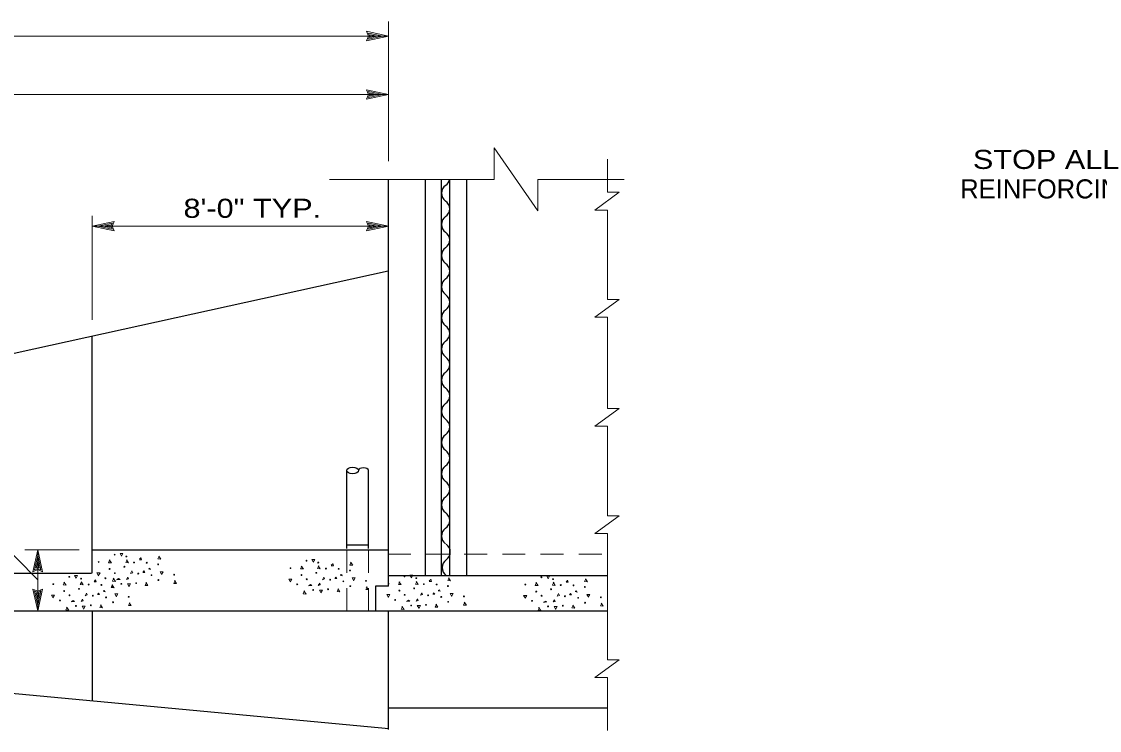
# Model space of a CAD drawing. Extents: x -22.3 to 19.7, y -11.8 to 18.2.
# Drawn here: x 5.45 to 12.51, y 1.6 to 6.24 of the extents above; entities that cross this region are included whole.
import ezdxf
from ezdxf.enums import TextEntityAlignment as Align

# ---------------------------------------------------------------- set-up
doc = ezdxf.new("R2010")
doc.units = 0
doc.header["$LTSCALE"] = 0.05
doc.linetypes.add('MEDIUM_DASHED', pattern=[4.5, 3, -1.5])
doc.layers.add('1', color=7, linetype='Continuous', lineweight=13)
doc.layers.add('2', color=7, linetype='Continuous', lineweight=13)

msp = doc.modelspace()

# ---------------------------------------------------------------- linework, layer by layer
at = {"layer": '1'}
for p, q in [((7.85258, 5.32831), (7.85258, 6.24331)), ((5.11858, 6.14831), (7.85258, 6.14831)), ((7.85258, 6.14831), (7.70858, 6.17931)), ((7.85258, 6.14831), (7.70858, 6.11731)), ((7.81558, 6.14831), (7.72158, 6.16831)), ((7.73058, 6.14831), (7.72158, 6.16831)), ((7.81558, 6.14831), (7.72158, 6.12831)), ((7.72158, 6.12831), (7.73058, 6.14831)), ((7.77958, 6.14831), (7.73458, 6.15731)), ((7.73858, 6.14831), (7.73458, 6.15731)), ((7.77958, 6.14831), (7.73458, 6.13831)), ((7.73458, 6.13831), (7.73858, 6.14831)), ((7.85258, 5.76631), (7.70858, 5.79731)), ((7.81558, 5.76631), (7.72158, 5.78631)), ((7.73058, 5.76631), (7.72158, 5.78631)), ((5.09858, 5.76631), (7.85258, 5.76631)), ((7.85258, 5.76631), (7.70858, 5.73531)), ((7.81558, 5.76631), (7.72158, 5.74631)), ((7.72158, 5.74631), (7.73058, 5.76631)), ((7.77958, 5.76631), (7.73458, 5.77531)), ((7.73858, 5.76631), (7.73458, 5.77531)), ((7.77958, 5.76631), (7.73458, 5.75631)), ((7.73458, 5.75631), (7.73858, 5.76631)), ((8.54558, 5.21031), (8.54558, 5.41631)), ((8.83058, 5.00331), (8.54558, 5.41631)), ((9.28658, 5.12531), (9.28658, 5.34231)), ((7.46758, 5.21031), (8.54558, 5.21031)), ((8.83058, 5.00331), (8.83058, 5.21031)), ((8.83058, 5.21031), (9.39658, 5.21031)), ((9.20458, 5.00931), (9.36258, 5.12531)), ((9.28658, 5.12531), (9.36258, 5.12531)), ((5.91358, 4.29031), (5.91358, 4.97031)), ((9.20458, 5.00931), (9.28658, 5.00931)), ((9.28658, 4.42331), (9.28658, 5.00931)), ((5.91358, 4.90331), (6.05758, 4.93431)), ((5.91358, 4.90331), (7.85258, 4.90331)), ((5.91358, 4.90331), (6.05758, 4.87231)), ((5.95058, 4.90331), (6.04458, 4.92331)), ((5.95058, 4.90331), (6.04458, 4.88331)), ((5.98658, 4.90331), (6.03158, 4.91331)), ((5.98658, 4.90331), (6.03158, 4.89431)), ((6.03158, 4.91331), (6.02758, 4.90331)), ((6.02758, 4.90331), (6.03158, 4.89431)), ((6.04458, 4.92331), (6.03558, 4.90331)), ((6.03558, 4.90331), (6.04458, 4.88331)), ((7.85258, 4.90331), (7.70858, 4.93431)), ((7.85258, 4.90331), (7.70858, 4.87231)), ((7.81558, 4.90331), (7.72158, 4.92331)), ((7.73058, 4.90331), (7.72158, 4.92331)), ((7.81558, 4.90331), (7.72158, 4.88331)), ((7.72158, 4.88331), (7.73058, 4.90331)), ((7.77958, 4.90331), (7.73458, 4.91231)), ((7.73858, 4.90331), (7.73458, 4.91231)), ((7.77958, 4.90331), (7.73458, 4.89331)), ((7.73458, 4.89331), (7.73858, 4.90331)), ((9.20458, 4.30731), (9.36258, 4.42331)), ((9.28658, 4.42331), (9.36258, 4.42331)), ((9.20458, 4.30731), (9.28658, 4.30731)), ((9.28658, 3.71031), (9.28658, 4.30731)), ((9.20458, 3.59431), (9.36258, 3.71031)), ((9.28658, 3.71031), (9.36258, 3.71031)), ((9.20458, 3.59431), (9.28658, 3.59431)), ((9.28658, 3.00831), (9.28658, 3.59431)), ((9.20458, 2.89231), (9.36258, 3.00831)), ((9.28658, 3.00831), (9.36258, 3.00831)), ((9.20458, 2.89231), (9.28658, 2.89231)), ((9.28658, 2.06531), (9.28658, 2.89231)), ((5.82758, 2.78531), (5.47258, 2.78531)), ((5.55658, 2.78531), (5.52558, 2.64131)), ((5.55658, 2.38431), (5.55658, 2.78531)), ((5.55658, 2.78531), (5.58758, 2.64131)), ((5.55658, 2.74831), (5.53658, 2.65431)), ((5.55658, 2.71231), (5.54758, 2.66731)), ((5.55658, 2.74831), (5.57658, 2.65431)), ((5.55658, 2.71231), (5.56658, 2.66731)), ((5.55658, 2.66331), (5.53658, 2.65431)), ((5.55658, 2.67131), (5.54758, 2.66731)), ((5.56658, 2.66731), (5.55658, 2.67131)), ((5.57658, 2.65431), (5.55658, 2.66331)), ((5.55658, 2.38431), (5.52558, 2.52831)), ((5.55658, 2.42131), (5.53658, 2.51531)), ((5.53658, 2.51531), (5.55658, 2.50631)), ((5.55658, 2.45731), (5.54658, 2.50231)), ((5.54658, 2.50231), (5.55658, 2.49831)), ((5.55658, 2.38431), (5.58758, 2.52831)), ((5.55658, 2.42131), (5.57658, 2.51531)), ((5.55658, 2.50631), (5.57658, 2.51531)), ((5.55658, 2.45731), (5.56558, 2.50231)), ((5.55658, 2.49831), (5.56558, 2.50231)), ((9.20458, 1.94931), (9.36258, 2.06531)), ((9.28658, 2.06531), (9.36258, 2.06531)), ((9.20458, 1.94931), (9.28658, 1.94931)), ((9.28658, 1.60231), (9.28658, 1.94931))]:
    msp.add_line(p, q, dxfattribs=at)
at = {"layer": '1', "lineweight": 25}
for p, q in [((7.85258, 2.54631), (7.85258, 5.21031)), ((8.09558, 2.61731), (8.09558, 5.21031)), ((8.19958, 2.61731), (8.19958, 5.21031)), ((8.25358, 2.61731), (8.25358, 5.21031)), ((8.36558, 2.61731), (8.36558, 5.21031)), ((5.16258, 4.01931), (7.85058, 4.61031)), ((5.91358, 2.63231), (5.91358, 4.18131)), ((7.57958, 2.79431), (7.57958, 3.30431)), ((7.72158, 2.79431), (7.72158, 3.30431)), ((5.91358, 2.78531), (7.84858, 2.78531)), ((7.57958, 2.81831), (7.72158, 2.81831)), ((5.16558, 2.63231), (5.90958, 2.63231)), ((7.85258, 2.61731), (9.28658, 2.61731)), ((5.16558, 2.38431), (9.28558, 2.38431)), ((5.91358, 2.38431), (5.91358, 1.79631)), ((7.85258, 1.60831), (7.85258, 2.38431)), ((5.16458, 1.86731), (7.85458, 1.61431)), ((7.85258, 1.75131), (9.28558, 1.75131))]:
    msp.add_line(p, q, dxfattribs=at)
at = {"layer": '1', "linetype": 'MEDIUM_DASHED'}
for p, q in [((7.57958, 2.38431), (7.57958, 2.79431)), ((7.72158, 2.38431), (7.72158, 2.79431)), ((7.84858, 2.75631), (9.28658, 2.75631))]:
    msp.add_line(p, q, dxfattribs=at)
at = {"layer": '1'}
for points in [[(7.70858, 6.11731), (7.72258, 6.14831), (7.70858, 6.17931)], [(7.70858, 5.73531), (7.72258, 5.76631), (7.70858, 5.79731)], [(6.05758, 4.93431), (6.04358, 4.90331), (6.05758, 4.87231)], [(7.70858, 4.87231), (7.72258, 4.90331), (7.70858, 4.93431)], [(5.55658, 2.58831), (4.71458, 3.44231), (4.71458, 3.65231)], [(5.58758, 2.64131), (5.55658, 2.65531), (5.52558, 2.64131)], [(5.52558, 2.52831), (5.55658, 2.51431), (5.58758, 2.52831)]]:
    msp.add_lwpolyline(points, dxfattribs=at)
at = {"layer": '1', "lineweight": 25}
msp.add_lwpolyline([(7.85258, 2.54631), (7.76758, 2.54631), (7.76758, 2.38331)], dxfattribs=at)
for centre, start, end in [((8.26108, 5.11931), 124.0772, 235.92281), ((8.19208, 5.22131), 304.0772, 349.69515), ((8.19208, 5.01731), 304.0772, 55.92281), ((8.26108, 4.91531), 124.0772, 235.92281), ((8.19208, 4.81331), 304.0772, 55.92281), ((8.26108, 4.71131), 124.0772, 235.92281), ((8.19208, 4.60931), 304.0772, 55.92281), ((8.26108, 4.50731), 124.0772, 235.92281), ((8.19208, 4.40531), 304.0772, 55.92281), ((8.26108, 4.30331), 124.0772, 235.92281), ((8.19208, 4.20131), 304.0772, 55.92281), ((8.26108, 4.09931), 124.0772, 235.92281), ((8.19208, 3.99731), 304.0772, 55.92281), ((8.26108, 3.89531), 124.0772, 235.92281), ((8.19208, 3.79331), 304.0772, 55.92281), ((8.26108, 3.69131), 124.0772, 235.92281), ((8.19208, 3.58931), 304.0772, 55.92281), ((8.26108, 3.48731), 124.0772, 235.92281), ((8.19208, 3.38531), 304.0772, 55.92281), ((8.26108, 3.28331), 124.0772, 235.92281), ((8.19208, 3.18131), 304.0772, 55.92281), ((8.26108, 3.07931), 124.0772, 235.92281), ((8.19208, 2.97731), 304.0772, 55.92281), ((8.26108, 2.87531), 124.0772, 235.92281), ((8.19608, 2.77031), 304.0772, 55.92281), ((8.26508, 2.66831), 124.0772, 235.92281)]:
    msp.add_arc(centre, 0.06157, start, end, dxfattribs=at)
msp.add_ellipse((7.61808, 3.30431), major_axis=(0.0385, 0), ratio=0.545501, dxfattribs=at)
msp.add_ellipse((7.68908, 3.30431), major_axis=(-0.0325, 0), ratio=0.528164, start_param=3.1415927, end_param=6.2831853, dxfattribs=at)
at = {"layer": '2'}
for p, q in [((6.22258, 2.72331), (6.23258, 2.73231)), ((7.47858, 2.68331), (7.48858, 2.69231)), ((5.92558, 2.57831), (5.93558, 2.58731)), ((8.11958, 2.58131), (8.12958, 2.59031)), ((9.01558, 2.57531), (9.02558, 2.58431))]:
    msp.add_line(p, q, dxfattribs=at)
for points in [[(6.10458, 2.74531), (6.09558, 2.76131), (6.11458, 2.76131), (6.10458, 2.74331)], [(6.02958, 2.71831), (6.02058, 2.70031), (6.03958, 2.69931), (6.02458, 2.71831)], [(6.14158, 2.72031), (6.13258, 2.70231), (6.15058, 2.70031), (6.13758, 2.72031)], [(6.23258, 2.73431), (6.23658, 2.72031), (6.22258, 2.72031)], [(6.35258, 2.74331), (6.34358, 2.72531), (6.36258, 2.72331), (6.34858, 2.74331)], [(7.36058, 2.70531), (7.35158, 2.72131), (7.37058, 2.72131), (7.36058, 2.70331)], [(7.48858, 2.69431), (7.49258, 2.68031), (7.47858, 2.68031)], [(7.60858, 2.70331), (7.59958, 2.68531), (7.61858, 2.68331), (7.60458, 2.70331)], [(5.80758, 2.60031), (5.79858, 2.61631), (5.81758, 2.61631), (5.80758, 2.59831)], [(5.95358, 2.61831), (5.94458, 2.63331), (5.96458, 2.63331), (5.95358, 2.61531)], [(6.24558, 2.63731), (6.25158, 2.64631), (6.25858, 2.63731), (6.24758, 2.63731)], [(6.28158, 2.66131), (6.29058, 2.66431), (6.29458, 2.65531), (6.28158, 2.65931)], [(6.36758, 2.62631), (6.35858, 2.64131), (6.37858, 2.64131), (6.36758, 2.62231)], [(7.28558, 2.67831), (7.27658, 2.66031), (7.29558, 2.65931), (7.28058, 2.67831)], [(7.39758, 2.68031), (7.38858, 2.66231), (7.40658, 2.66031), (7.39358, 2.68031)], [(7.53758, 2.62131), (7.54658, 2.62431), (7.55058, 2.61531), (7.53758, 2.61931)], [(8.00158, 2.60331), (7.99258, 2.61931), (8.01158, 2.61931), (8.00158, 2.60131)], [(8.89758, 2.59731), (8.88858, 2.61331), (8.90758, 2.61331), (8.89758, 2.59531)], [(5.73258, 2.57331), (5.72358, 2.55531), (5.74258, 2.55431), (5.72758, 2.57331)], [(5.84458, 2.57531), (5.83558, 2.55731), (5.85358, 2.55531), (5.84058, 2.57531)], [(5.93558, 2.58931), (5.93958, 2.57531), (5.92558, 2.57531)], [(6.04758, 2.55531), (6.03858, 2.53731), (6.05758, 2.53531), (6.04258, 2.55531)], [(6.05558, 2.59831), (6.04658, 2.58031), (6.06558, 2.57831), (6.05158, 2.59831)], [(6.07758, 2.59131), (6.08658, 2.59731), (6.09558, 2.59131), (6.07358, 2.58831)], [(6.15358, 2.54631), (6.14458, 2.56131), (6.16458, 2.56131), (6.15358, 2.54231)], [(6.26958, 2.57031), (6.26058, 2.55231), (6.27858, 2.55031), (6.26558, 2.57031)], [(6.45658, 2.58331), (6.44758, 2.56531), (6.46558, 2.56431), (6.45158, 2.58331)], [(7.20958, 2.57831), (7.20058, 2.59331), (7.22058, 2.59331), (7.20958, 2.57531)], [(7.33358, 2.55131), (7.34258, 2.55731), (7.35158, 2.55131), (7.32958, 2.54831)], [(7.50158, 2.59731), (7.50758, 2.60631), (7.51458, 2.59731), (7.50358, 2.59731)], [(7.62358, 2.58631), (7.61458, 2.60131), (7.63458, 2.60131), (7.62358, 2.58231)], [(7.71258, 2.54331), (7.70358, 2.52531), (7.72158, 2.52431), (7.70758, 2.54331)], [(7.92658, 2.57631), (7.91758, 2.55831), (7.93658, 2.55731), (7.92158, 2.57631)], [(8.03858, 2.57831), (8.02958, 2.56031), (8.04758, 2.55831), (8.03458, 2.57831)], [(8.12958, 2.59231), (8.13358, 2.57831), (8.11958, 2.57831)], [(8.24958, 2.60131), (8.24058, 2.58331), (8.25958, 2.58131), (8.24558, 2.60131)], [(8.82258, 2.57031), (8.81358, 2.55231), (8.83258, 2.55131), (8.81758, 2.57031)], [(8.93458, 2.57231), (8.92558, 2.55431), (8.94358, 2.55231), (8.93058, 2.57231)], [(9.02558, 2.58631), (9.02958, 2.57231), (9.01558, 2.57231)], [(9.14558, 2.59531), (9.13658, 2.57731), (9.15558, 2.57531), (9.14158, 2.59531)], [(5.65658, 2.47331), (5.64758, 2.48831), (5.66758, 2.48831), (5.65658, 2.47031)], [(5.94858, 2.49231), (5.95458, 2.50131), (5.96158, 2.49231), (5.95058, 2.49231)], [(5.98458, 2.51631), (5.99358, 2.51931), (5.99758, 2.51031), (5.98458, 2.51431)], [(6.07058, 2.48131), (6.06158, 2.49631), (6.08158, 2.49631), (6.07058, 2.47731)], [(7.30358, 2.51531), (7.29458, 2.49731), (7.31358, 2.49531), (7.29858, 2.51531)], [(7.40958, 2.50631), (7.40058, 2.52131), (7.42058, 2.52131), (7.40958, 2.50231)], [(7.52558, 2.53031), (7.51658, 2.51231), (7.53458, 2.51031), (7.52158, 2.53031)], [(7.85058, 2.47631), (7.84158, 2.49131), (7.86158, 2.49131), (7.85058, 2.47331)], [(8.14258, 2.49531), (8.14858, 2.50431), (8.15558, 2.49531), (8.14458, 2.49531)], [(8.17858, 2.51931), (8.18758, 2.52231), (8.19158, 2.51331), (8.17858, 2.51731)], [(8.26458, 2.48431), (8.25558, 2.49931), (8.27558, 2.49931), (8.26458, 2.48031)], [(8.74658, 2.47031), (8.73758, 2.48531), (8.75758, 2.48531), (8.74658, 2.46731)], [(9.03858, 2.48931), (9.04458, 2.49831), (9.05158, 2.48931), (9.04058, 2.48931)], [(9.07458, 2.51331), (9.08358, 2.51631), (9.08758, 2.50731), (9.07458, 2.51131)], [(9.16058, 2.47831), (9.15158, 2.49331), (9.17158, 2.49331), (9.16058, 2.47431)], [(5.75058, 2.41031), (5.74158, 2.39231), (5.76058, 2.39031), (5.74558, 2.41031)], [(5.78058, 2.44631), (5.78958, 2.45231), (5.79858, 2.44631), (5.77658, 2.44331)], [(5.85658, 2.40131), (5.84758, 2.41631), (5.86758, 2.41631), (5.85658, 2.39731)], [(5.97258, 2.42531), (5.96358, 2.40731), (5.98158, 2.40531), (5.96858, 2.42531)], [(6.15958, 2.43831), (6.15058, 2.42031), (6.16858, 2.41931), (6.15458, 2.43831)], [(7.94458, 2.41331), (7.93558, 2.39531), (7.95458, 2.39331), (7.93958, 2.41331)], [(7.97458, 2.44931), (7.98358, 2.45531), (7.99258, 2.44931), (7.97058, 2.44631)], [(8.05058, 2.40431), (8.04158, 2.41931), (8.06158, 2.41931), (8.05058, 2.40031)], [(8.16658, 2.42831), (8.15758, 2.41031), (8.17558, 2.40831), (8.16258, 2.42831)], [(8.35358, 2.44131), (8.34458, 2.42331), (8.36258, 2.42231), (8.34858, 2.44131)], [(8.84058, 2.40731), (8.83158, 2.38931), (8.85058, 2.38731), (8.83558, 2.40731)], [(8.87058, 2.44331), (8.87958, 2.44931), (8.88858, 2.44331), (8.86658, 2.44031)], [(8.94658, 2.39831), (8.93758, 2.41331), (8.95758, 2.41331), (8.94658, 2.39431)], [(9.06258, 2.42231), (9.05358, 2.40431), (9.07158, 2.40231), (9.05858, 2.42231)], [(9.24958, 2.43531), (9.24058, 2.41731), (9.25858, 2.41631), (9.24458, 2.43531)]]:
    msp.add_lwpolyline(points, dxfattribs=at)
for points in [[(6.16458, 2.62931), (6.17358, 2.64631), (6.17858, 2.63431)], [(6.13758, 2.59131), (6.14658, 2.60631), (6.15058, 2.59531)], [(7.39358, 2.55131), (7.40258, 2.56631), (7.40658, 2.55531)], [(7.42058, 2.58931), (7.42958, 2.60631), (7.43458, 2.59431)], [(5.86758, 2.48431), (5.87658, 2.50131), (5.88158, 2.48931)], [(8.06158, 2.48731), (8.07058, 2.50431), (8.07558, 2.49231)], [(8.95758, 2.48131), (8.96658, 2.49831), (8.97158, 2.48631)], [(5.84058, 2.44631), (5.84958, 2.46131), (5.85358, 2.45031)], [(8.03458, 2.44931), (8.04358, 2.46431), (8.04758, 2.45331)], [(8.93058, 2.44331), (8.93958, 2.45831), (8.94358, 2.44731)]]:
    msp.add_lwpolyline(points, close=True, dxfattribs=at)
for centre in [(6.06053, 2.75314), (5.95568, 2.70499), (6.13748, 2.74099), (6.18743, 2.70184), (6.27068, 2.70004), (6.34493, 2.68969), (7.31653, 2.71314), (7.39348, 2.70099), (5.76353, 2.60814), (6.02723, 2.65954), (6.06188, 2.63209), (6.12398, 2.67439), (6.21488, 2.62894), (6.30128, 2.61859), (6.44978, 2.62174), (7.21168, 2.66499), (7.28323, 2.61954), (7.37998, 2.63439), (7.44343, 2.66184), (7.52668, 2.66004), (7.60093, 2.64969), (7.95753, 2.61114), (5.65868, 2.55999), (5.84048, 2.59599), (5.89043, 2.55684), (5.97368, 2.55504), (5.99978, 2.59879), (6.04793, 2.54469), (6.10418, 2.56234), (6.20138, 2.56684), (6.34673, 2.58664), (7.25578, 2.55879), (7.31788, 2.59209), (7.47088, 2.58894), (7.55728, 2.57859), (7.60273, 2.54664), (7.70578, 2.58174), (7.85268, 2.56299), (8.03448, 2.59899), (8.08443, 2.55984), (8.16768, 2.55804), (8.24193, 2.54769), (8.74868, 2.55699), (8.85353, 2.60514), (8.93048, 2.59299), (8.98043, 2.55384), (9.06368, 2.55204), (9.13793, 2.54169), (5.73023, 2.51454), (5.76488, 2.48709), (5.82698, 2.52939), (5.91788, 2.48394), (6.00428, 2.47359), (6.15278, 2.47674), (7.36018, 2.52234), (7.45738, 2.52684), (7.92423, 2.51754), (7.95888, 2.49009), (8.02098, 2.53239), (8.11188, 2.48694), (8.19828, 2.47659), (8.34678, 2.47974), (8.82023, 2.51154), (8.85488, 2.48409), (8.91698, 2.52639), (9.00788, 2.48094), (9.09428, 2.47059), (9.24278, 2.47374), (5.70278, 2.45379), (5.80718, 2.41734), (5.90438, 2.42184), (6.04973, 2.44164), (7.89678, 2.45679), (8.00118, 2.42034), (8.09838, 2.42484), (8.24373, 2.44464), (8.79278, 2.45079), (8.89718, 2.41434), (8.99438, 2.41884), (9.13973, 2.43864)]:
    msp.add_circle(centre, 0.00293, dxfattribs=at)

# ---------------------------------------------------------------- texts
at = {"layer": '1', "width": 1.2}
for s, p in [('STOP ALL', (12.15758, 5.27831)), ('8\'-0" TYP.', (6.96158, 4.95831))]:
    msp.add_text(s, height=0.125, dxfattribs=at).set_placement(p, align=Align.CENTER)
at = {"layer": '1'}
msp.add_text('REINFORCING', height=0.125, dxfattribs=at).set_placement((12.76558, 5.08531), align=Align.RIGHT)

doc.saveas('drawing.dxf')
